(* Logix 5000 project; controller MVI56MCM 1756-L63 rev 15.3; software revision 15.00 *)
// Example Logic for the MVI56-MCM module.

TASK MainTask (continuous, watchdog 500 ms) : MainProgram

MODULES
   Local : 1756-L63 (ICP 0, rev 15.3)
      MVI56MCM : vendor 1 type 0 code 15 (ICP 1, rev 1.1, Output RPI 2 ms)   // ProSoft Technology Modbus communication module for the control logix platform
END_MODULES

TYPE _CmdControl :
STRUCT
   TriggerCmdCntrl : BOOL;   // Trigger command control. User application will activate this trigger
   NumberOfCommands : INT;   // Number of commands per block (1 to 6)
   PortNumber : INT;   // MVI56-MCM Port Number of master port (1 or 2)
   CommandIndex : INT[6];   // Stores the command indexes for command control
   CmdsAddedToQueue : INT;   // Number of commands added to queue
   CmdControlBlockID : INT;   // Temporary variable to calculate control block ID
   CmdCntrlPending : BOOL;   // Auxiliary control command - prevents a second request before acknowledgment is received
END_STRUCT
END_TYPE

TYPE _CoilArray :   // Conversion to INT values
STRUCT
   Boolean : BOOL[416];   // Conversion from Bool to INT data types
END_STRUCT
END_TYPE

TYPE _EventCmd :
STRUCT
   EventCmdTrigger : BOOL;   // Trigger for event command. User ladder must set this bit to initiate event command
   EventCmdPending : BOOL;   // Set after the ladder has sent an event cmd to the module and is waiting for the status to be returned
   PortNumber : INT;   // Module master port number associated to this request (1 or 2)
   SlaveAddress : INT;   // Slave target modbus address
   InternalDBAddress : INT;   // Internal database address
   PointCount : INT;   // Number of points for this command
   SwapCode : INT;   // Swap code (0= no swap, 1=swap words, 2=swap words and bytes, 3=swap bytes)
   ModbusFunctionCode : INT;   // Modbus function code
   DeviceDBAddress : INT;   // Modbus register address in target modbus slave
   EventCmdStatusReturned : INT;   // (0=Fail, 1=Sucess)
   EventBlockID : INT;   // Temporary variable to calculate event block ID
END_STRUCT
END_TYPE

TYPE _Passthru :
STRUCT
   MBOffset : INT;
   MBOffsetBit : INT;
   MBMsgLen : INT;
   MBMsg : SINT[500];
   MBControl1 : CONTROL;
   MBControl2 : CONTROL;
   MBScratch : INT[3];
   MBCoil : _CoilArray;
END_STRUCT
END_TYPE

TYPE _SlavePollStatus :   // This object contains all of the Slave Polling status (used when the port is used as a master)
STRUCT
   Port1Slave0Read : BOOL;
   Port1Slave128Read : BOOL;
   Port2Slave0Read : BOOL;
   Port2Slave128Read : BOOL;
   P1Slaves : INT[256];   // P1 Slave Status
   P2Slaves : INT[256];   // P2 Slave Status
END_STRUCT
END_TYPE

TYPE _Util :   // This object contains optional elements for the module.
STRUCT
   CmdControl : _CmdControl;   // Allows for a disabled command to be sent to a device (MASTER)
   EventCmd : _EventCmd;   // Allows a command defined in ladder to be sent to a device (MASTER)
   SlavePollStat : _SlavePollStatus;   // Request slave poll status for the port (MASTER).
   Passthru : _Passthru;   // Contains PassThru objects required when PortX.Type is set to a value between 2-4.
END_STRUCT
END_TYPE

TYPE MCMBlkStat :   // This object is used to store the block transfer statistics for the module.
STRUCT
   Read : INT;   // Total number of read block transfers
   Write : INT;   // Total number of write block transfers
   Parse : INT;   // Total number of blocks parsed
   Event : INT;   // Total number of event blocks received
   Cmd : INT;   // Total number of command blocks received
   Err : INT;   // Total number of block transfer errors
END_STRUCT
END_TYPE

TYPE MCMCmd :   // This object is used to contain the attributes to define a master command. An array of these objects is used for each port.
STRUCT
   Enable : INT;   // 0=Disable,1=Continuous,2=Event Command
   IntAddress : INT;   // Module's internal address associated with the command
   PollInt : INT;   // Minimum number of seconds between issuance of command (0-65535 Sec)
   Count : INT;   // Number of registers associated with the command
   Swap : INT;   // Swap code used with command
   Node : INT;   // Node address of the target device on the network
   Func : INT;   // Function code for the command
   DevAddress : INT;   // Address in device associated with the command
END_STRUCT
END_TYPE

TYPE MCMCONFIG :
STRUCT
   ModDef : MCMModule;   // Module Defintion
   Port1 : MCMPort;   // Port 1 configuration settings
   Port2 : MCMPort;   // Port 2 configuration settings
   Port1MasterCmd : MCMCmd[100];   // Master commands for Port 1 (ignore if port is configured for slave mode)
   Port2MasterCmd : MCMCmd[100];   // Master commands for Port 2 (ignore if port is configured for slave mode)
END_STRUCT
END_TYPE

TYPE MCMCONTROL :
STRUCT
   WarmBoot : BOOL;
   ColdBoot : BOOL;
   BPLastRead : INT;   // Index of last read block
   BPLastWrite : INT;   // Index of last write block
   BlockIndex : INT;   // Computed block offset for data table
END_STRUCT
END_TYPE

TYPE MCMDATA :   // Contains Read Data (data read from the module to the processor) and Write Data (data written from the processor to the module)
STRUCT
   ReadData : INT[600];   // Data read from the module to the processor
   WriteData : INT[600];   // Data written from the processor to the module
END_STRUCT
END_TYPE

TYPE MCMModule :   // This object contains the information used to define the data movement between the module and the processor.
STRUCT
   WriteStartReg : INT;   // Start reg to transfer from PLC to module
   WriteRegCnt : INT;   // Number of registers to write from PLC
   ReadStartReg : INT;   // Start reg to transfer from module to PLC
   ReadRegCnt : INT;   // Number of registers to transfer from module
   BPFail : INT;   // Determines module operation if BP fails 0=continue,>0=number of retries before comm shutdown
   ErrStatPtr : INT;   // Internal DB start register for status data (-1=Ignore)
END_STRUCT
END_TYPE

TYPE MCMModuleDef :
STRUCT
   CONFIG : MCMCONFIG;   // Module and port configuration
   DATA : MCMDATA;   // Modbus data transferred between module and processor
   STATUS : MCMSTATUS;   // Status information in each read block
   CONTROL : MCMCONTROL;   // Optional requests from the processor to the module
   _UTIL : _Util;   // Variables for internal ladder usage - should not be accessed by user application
END_STRUCT
END_TYPE

TYPE MCMPort :   // The serial port configuration for the MVI56MCM module.
STRUCT
   Enabled : INT;   // O=Port Disabled,1=Port Enabled
   Type : INT;   // 0=Master, 1=Slave, 2=Slave: pass-through, 3=Slave: formatted pass-through/data swapped, 4=Slave: form. pass-through
   FloatFlag : INT;   // 0=No floating-point data, 1=Use floating-point data
   FloatStart : INT;   // Register offset in message for floating-point data
   FloatOffset : INT;   // Internal DB offset to start of floating-point data
   Protocol : INT;   // 0=Modbus RTU, 1=Modbus ASCII
   Baudrate : INT;   // Baudrate for port (110 to 115.2K)
   Parity : INT;   // 0=None, 1=Odd, 2=Even, 3=Mark, 4=Space
   DataBits : INT;   // 5 to 8 data bits
   StopBits : INT;   // 1 or 2 stop bits
   RTSOn : INT;   // 0-65535 mSec delay before data
   RTSOff : INT;   // 0-65535 mSec delay after data
   MinResp : INT;   // 0-65535 mSec minimum time before response to request
   UseCTS : INT;   // 0=No, 1=Yes to use CTS modem line
   SlaveID : INT;   // 1-255 Modbus Node Address (Slave)
   BitInOffset : INT;   // Internal DB offset to bit input data (Slave)
   WordInOffset : INT;   // Internal DB offset to word input data (Slave)
   OutOffset : INT;   // Internal DB offset to bit output data (Slave)
   HoldOffset : INT;   // Internal DB offset to holding register data (Slave)
   CmdCount : INT;   // Command list count (Master)
   MinCmdDelay : INT;   // 0-65535 mSec minimum time between each command (Master)
   CmdErrPtr : INT;   // Internal DB location to place command error list (Master)
   RespTO : INT;   // 0-65535 mSec response timeout for command (Master)
   RetryCount : INT;   // Retry count for failed request (Master)
   ErrorDelayCntr : INT;   // 0-65535 Command cycle count if error (Master)
   Reserved : INT;   // Reserved (Previously was UseGuardBand parameter)
   InterCharacterDelay : INT;   // 0-65535 mSec time between characters to signal end of message
   Fcn99Offset : INT;   // Internal DB offset to function 99 counter
END_STRUCT
END_TYPE

TYPE MCMPortErrors :   // This object is used to store the port statistics for an MVI56-MCM port.
STRUCT
   CmdReq : INT;   // Total number of command list requests sent
   CmdResp : INT;   // Total number of command list responses received
   CmdErr : INT;   // Total number of command list errors
   Requests : INT;   // Total number of requests for port
   Responses : INT;   // Total number of responses for port
   ErrSent : INT;   // Total number of errors sent
   ErrRec : INT;   // Total number of errors received
END_STRUCT
END_TYPE

TYPE MCMSTATUS :   // This status data is returned on each read block and can be used to detect proper module operation.
STRUCT
   PassCnt : INT;   // Program cycle counter
   Product : INT[2];   // Product Name
   Rev : INT[2];   // Revision Level Number
   OP : INT[2];   // Operating Level Number
   Run : INT[2];   // Run Number
   Prt1Errs : MCMPortErrors;   // Port 1 error statistics
   Prt2Errs : MCMPortErrors;   // Port 2 error statistics
   Blk : MCMBlkStat;   // Block transfer statistics
   Port1LastErr : INT;   // Last command index that received an error on Port 1
   Port1PreviousErr : INT;   // Previous Command index that received an error on Port 1
   Port2LastErr : INT;   // Last command index that received an error on Port 2
   Port2PreviousErr : INT;   // Previous Command index that received an error on Port 2
END_STRUCT
END_TYPE

VAR_GLOBAL   (* controller tags *)
   MCM : MCMModuleDef;
        ._UTIL.PASSTHRU.MBCONTROL1.LEN   // Number of words
        ._UTIL.PASSTHRU.MBSCRATCH[2]   // Moves value
        ._UTIL.PASSTHRU.MBMSGLEN   // Copies write message length to MBMsgLen field
        ._UTIL.PASSTHRU.MBOFFSET   // Word Address
        ._UTIL.PASSTHRU.MBMSG[0]   // Copies the rest of the modbus write message from the master to the MBMsg field
        ._UTIL.PASSTHRU.MBOFFSETBIT   // Sets up bit to be changed
        .DATA.WRITEDATA[0]   // Copies changed data back to WriteData array
        ._UTIL.PASSTHRU.MBCOIL   // Copies WriteData to MBCoil array
        ._UTIL.PASSTHRU.MBCONTROL2.LEN   // Number of words
        ._UTIL.PASSTHRU.MBCONTROL1   // AND's new data with bit mask
        ._UTIL.PASSTHRU.MBCONTROL2   // New data ANDed with mask and ORed with existing data
   MJFAULTS : DINT[12] := ([0] := 450621270, [1] := 191890, [3] := 236704315, [4] := 191890);
END_VAR

PROGRAM MainProgram   (* main routine MainRoutine *)

ROUTINE _PassThru   (* ladder *)
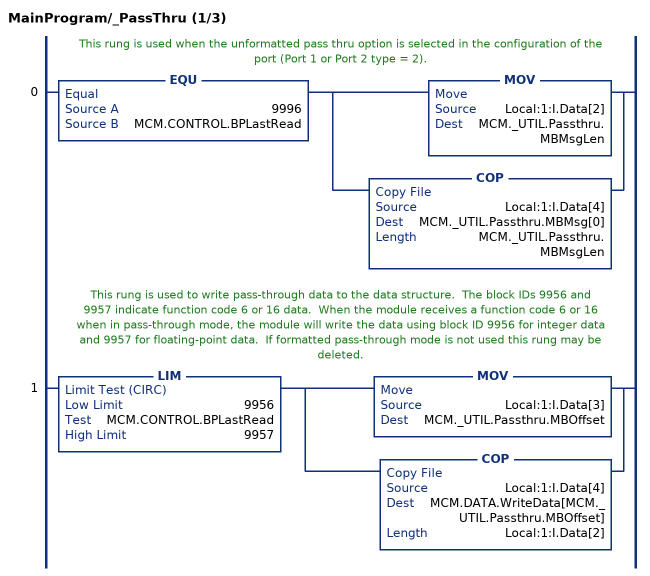
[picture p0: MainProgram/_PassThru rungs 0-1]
   // This rung is used when the unformatted pass thru option is selected in the configuration of the port (Port 1 or Port 2 type = 2).
   0: EQU(9996,MCM.CONTROL.BPLastRead)[MOV(Local:1:I.Data[2],MCM._UTIL.Passthru.MBMsgLen) ,COP(Local:1:I.Data[4],MCM._UTIL.Passthru.MBMsg[0],MCM._UTIL.Passthru.MBMsgLen) ];
   // This rung is used to write pass-through data to the data structure.  The block IDs 9956 and 9957 indicate function code 6 or 16 data.  When the module receives a function code 6 or 16 when in pass-through mode, the module will write the data using block ID 9956 for integer data and 9957 for floating-point data.  If formatted pass-through mode is not used this rung may be deleted.
   1: LIM(9956,MCM.CONTROL.BPLastRead,9957)[MOV(Local:1:I.Data[3],MCM._UTIL.Passthru.MBOffset) ,COP(Local:1:I.Data[4],MCM.DATA.WriteData[MCM._UTIL.Passthru.MBOffset],Local:1:I.Data[2]) ];
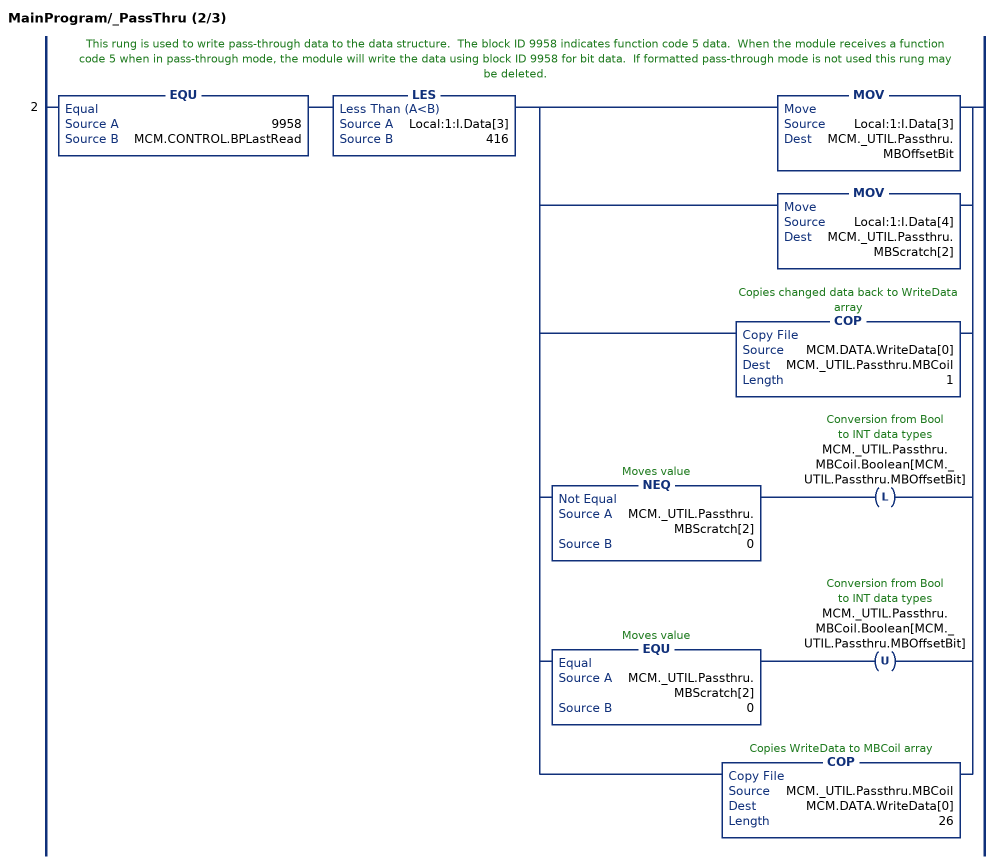
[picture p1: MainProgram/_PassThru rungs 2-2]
   // This rung is used to write pass-through data to the data structure.  The block ID 9958 indicates function code 5 data.  When the module receives a function code 5 when in pass-through mode, the module will write the data using block ID 9958 for bit data.  If formatted pass-through mode is not used this rung may be deleted.
   2: EQU(9958,MCM.CONTROL.BPLastRead)LES(Local:1:I.Data[3],416)[MOV(Local:1:I.Data[3],MCM._UTIL.Passthru.MBOffsetBit) ,MOV(Local:1:I.Data[4],MCM._UTIL.Passthru.MBScratch[2]) ,COP(MCM.DATA.WriteData[0],MCM._UTIL.Passthru.MBCoil,1) ,NEQ(MCM._UTIL.Passthru.MBScratch[2],0) OTL(MCM._UTIL.Passthru.MBCoil.Boolean[MCM._UTIL.Passthru.MBOffsetBit]) ,EQU(MCM._UTIL.Passthru.MBScratch[2],0) OTU(MCM._UTIL.Passthru.MBCoil.Boolean[MCM._UTIL.Passthru.MBOffsetBit]) ,COP(MCM._UTIL.Passthru.MBCoil,MCM.DATA.WriteData[0],26) ];
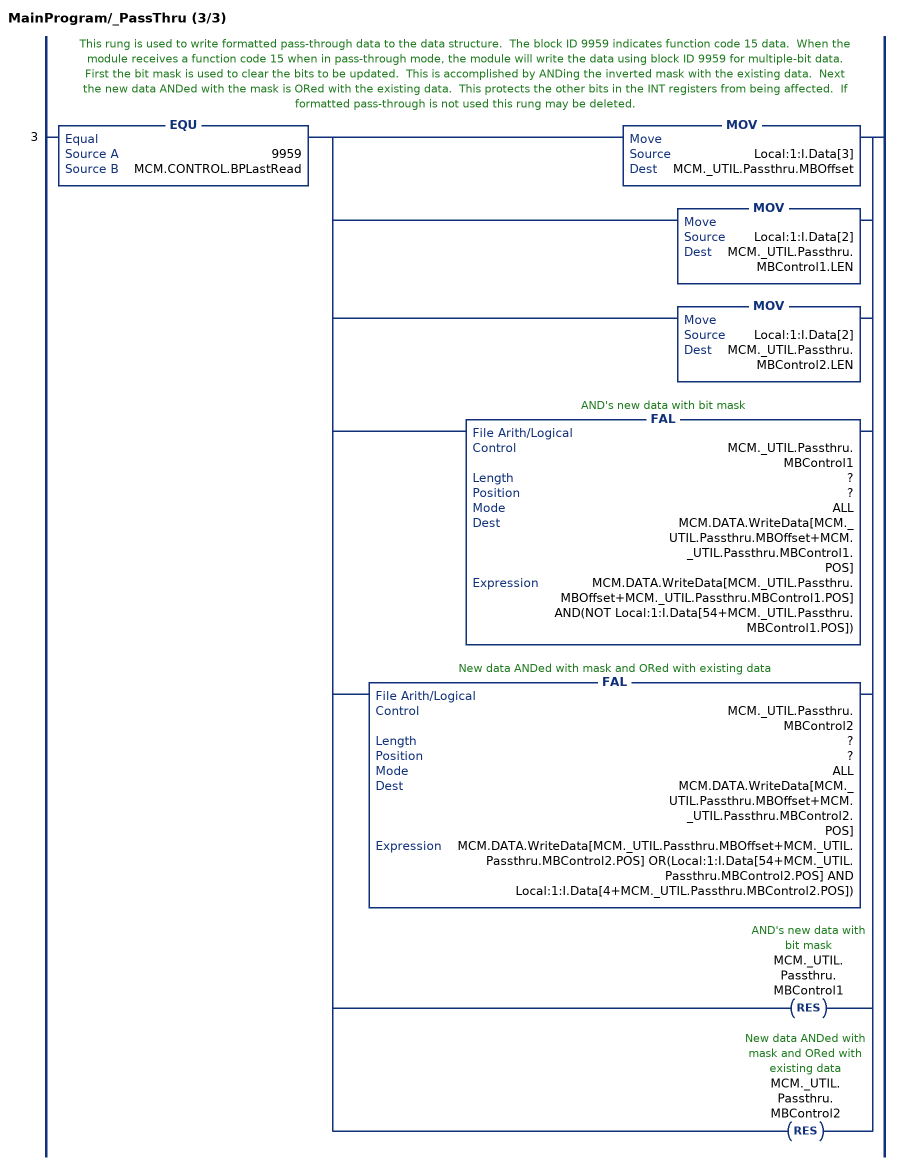
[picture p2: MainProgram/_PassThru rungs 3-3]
   // This rung is used to write formatted pass-through data to the data structure.  The block ID 9959 indicates function code 15 data.  When the module receives a function code 15 when in pass-through mode, the module will write the data using block ID 9959 for multiple-bit data.  First the bit mask is used to clear the bits to be updated.  This is accomplished by ANDing the inverted mask with the existing data.  Next the new data ANDed with the mask is ORed with the existing data.  This protects the other bits in the INT registers from being affected.  If formatted pass-through is not used this rung may be deleted.
   3: EQU(9959,MCM.CONTROL.BPLastRead)[MOV(Local:1:I.Data[3],MCM._UTIL.Passthru.MBOffset) ,MOV(Local:1:I.Data[2],MCM._UTIL.Passthru.MBControl1.LEN) ,MOV(Local:1:I.Data[2],MCM._UTIL.Passthru.MBControl2.LEN) ,FAL(MCM._UTIL.Passthru.MBControl1,?,?,ALL,MCM.DATA.WriteData[MCM._UTIL.Passthru.MBOffset+MCM._UTIL.Passthru.MBControl1.POS],MCM.DATA.WriteData[MCM._UTIL.Passthru.MBOffset+MCM._UTIL.Passthru.MBControl1.POS] AND(NOT Local:1:I.Data[54+MCM._UTIL.Passthru.MBControl1.POS])) ,FAL(MCM._UTIL.Passthru.MBControl2,?,?,ALL,MCM.DATA.WriteData[MCM._UTIL.Passthru.MBOffset+MCM._UTIL.Passthru.MBControl2.POS],MCM.DATA.WriteData[MCM._UTIL.Passthru.MBOffset+MCM._UTIL.Passthru.MBControl2.POS] OR(Local:1:I.Data[54+MCM._UTIL.Passthru.MBControl2.POS] AND Local:1:I.Data[4+MCM._UTIL.Passthru.MBControl2.POS])) ,RES(MCM._UTIL.Passthru.MBControl1) ,RES(MCM._UTIL.Passthru.MBControl2) ];
END_ROUTINE

ROUTINE _ReadControl   (* ladder *)
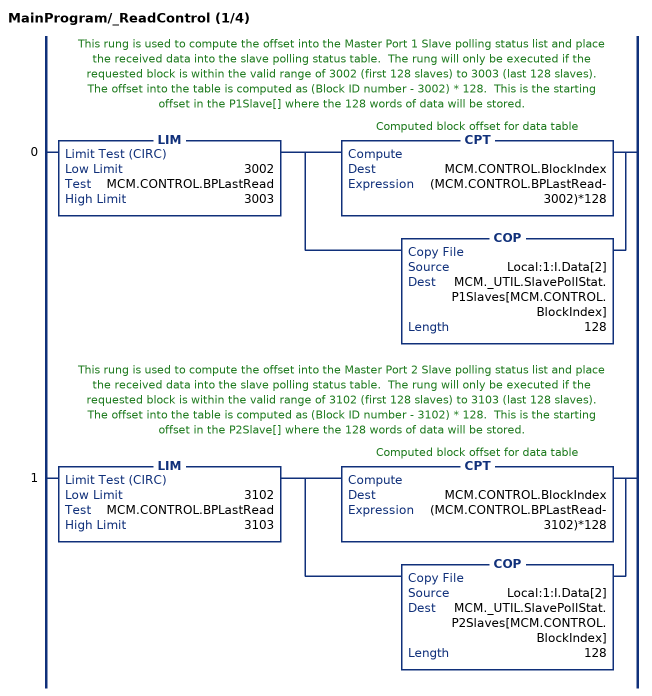
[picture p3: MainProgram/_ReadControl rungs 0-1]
   // This rung is used to compute the offset into the Master Port 1 Slave polling status list and place the received data into the slave polling status table.  The rung will only be executed if the requested block is within the valid range of 3002 (first 128 slaves) to 3003 (last 128 slaves).  The offset into the table is computed as (Block ID number - 3002) * 128.  This is the starting offset in the P1Slave[] where the 128 words of data will be stored.
   0: LIM(3002,MCM.CONTROL.BPLastRead,3003)[CPT(MCM.CONTROL.BlockIndex,(MCM.CONTROL.BPLastRead-3002)*128) ,COP(Local:1:I.Data[2],MCM._UTIL.SlavePollStat.P1Slaves[MCM.CONTROL.BlockIndex],128) ];
   // This rung is used to compute the offset into the Master Port 2 Slave polling status list and place the received data into the slave polling status table.  The rung will only be executed if the requested block is within the valid range of 3102 (first 128 slaves) to 3103 (last 128 slaves).  The offset into the table is computed as (Block ID number - 3102) * 128.  This is the starting offset in the P2Slave[] where the 128 words of data will be stored.
   1: LIM(3102,MCM.CONTROL.BPLastRead,3103)[CPT(MCM.CONTROL.BlockIndex,(MCM.CONTROL.BPLastRead-3102)*128) ,COP(Local:1:I.Data[2],MCM._UTIL.SlavePollStat.P2Slaves[MCM.CONTROL.BlockIndex],128) ];
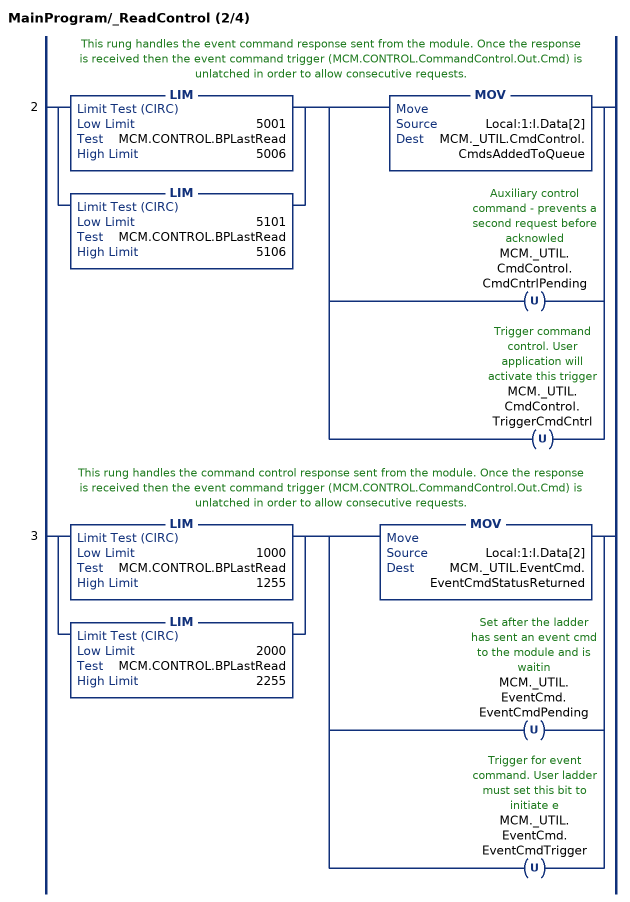
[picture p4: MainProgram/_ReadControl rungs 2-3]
   // This rung handles the event command response sent from the module. Once the response is received then the event command trigger (MCM.CONTROL.CommandControl.Out.Cmd) is unlatched in order to allow consecutive requests.
   2: [LIM(5001,MCM.CONTROL.BPLastRead,5006) ,LIM(5101,MCM.CONTROL.BPLastRead,5106) ][MOV(Local:1:I.Data[2],MCM._UTIL.CmdControl.CmdsAddedToQueue) ,OTU(MCM._UTIL.CmdControl.CmdCntrlPending) ,OTU(MCM._UTIL.CmdControl.TriggerCmdCntrl) ];
   // This rung handles the command control response sent from the module. Once the response is received then the event command trigger (MCM.CONTROL.CommandControl.Out.Cmd) is unlatched in order to allow consecutive requests.
   3: [LIM(1000,MCM.CONTROL.BPLastRead,1255) ,LIM(2000,MCM.CONTROL.BPLastRead,2255) ][MOV(Local:1:I.Data[2],MCM._UTIL.EventCmd.EventCmdStatusReturned) ,OTU(MCM._UTIL.EventCmd.EventCmdPending) ,OTU(MCM._UTIL.EventCmd.EventCmdTrigger) ];
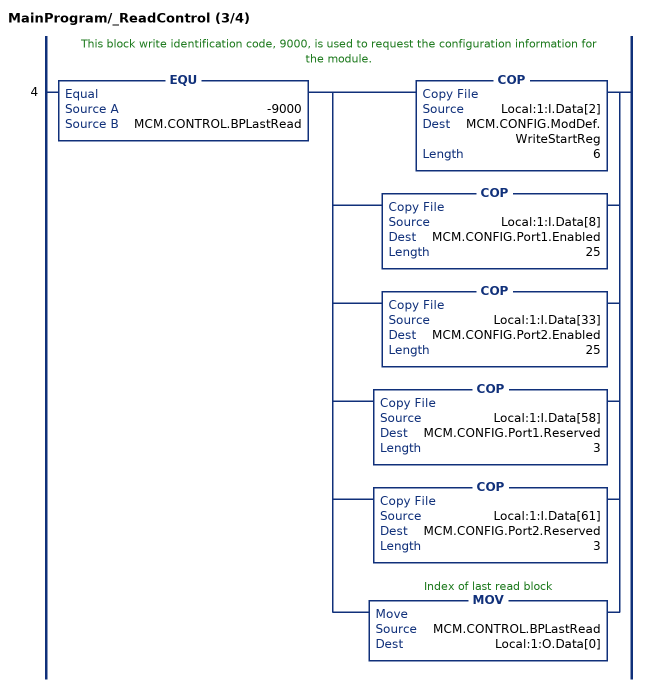
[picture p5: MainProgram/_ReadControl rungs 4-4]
   // This block write identification code, 9000, is used to request the configuration information for the module.
   4: EQU(-9000,MCM.CONTROL.BPLastRead)[COP(Local:1:I.Data[2],MCM.CONFIG.ModDef.WriteStartReg,6) ,COP(Local:1:I.Data[8],MCM.CONFIG.Port1.Enabled,25) ,COP(Local:1:I.Data[33],MCM.CONFIG.Port2.Enabled,25) ,COP(Local:1:I.Data[58],MCM.CONFIG.Port1.Reserved,3) ,COP(Local:1:I.Data[61],MCM.CONFIG.Port2.Reserved,3) ,MOV(MCM.CONTROL.BPLastRead,Local:1:O.Data[0]) ];
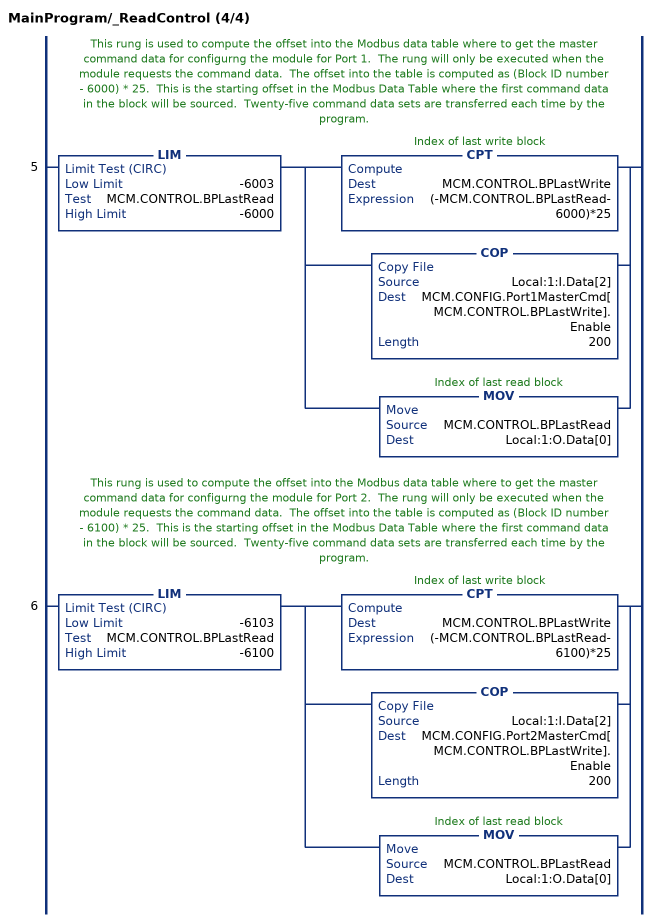
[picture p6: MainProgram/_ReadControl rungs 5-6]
   // This rung is used to compute the offset into the Modbus data table where to get the master command data for configurng the module for Port 1.  The rung will only be executed when the module requests the command data.  The offset into the table is computed as (Block ID number - 6000) * 25.  This is the starting offset in the Modbus Data Table where the first command data in the block will be sourced.  Twenty-five command data sets are transferred each time by the program.
   5: LIM(-6003,MCM.CONTROL.BPLastRead,-6000)[CPT(MCM.CONTROL.BPLastWrite,(-MCM.CONTROL.BPLastRead-6000)*25) ,COP(Local:1:I.Data[2],MCM.CONFIG.Port1MasterCmd[MCM.CONTROL.BPLastWrite].Enable,200) ,MOV(MCM.CONTROL.BPLastRead,Local:1:O.Data[0]) ];
   // This rung is used to compute the offset into the Modbus data table where to get the master command data for configurng the module for Port 2.  The rung will only be executed when the module requests the command data.  The offset into the table is computed as (Block ID number - 6100) * 25.  This is the starting offset in the Modbus Data Table where the first command data in the block will be sourced.  Twenty-five command data sets are transferred each time by the program.
   6: LIM(-6103,MCM.CONTROL.BPLastRead,-6100)[CPT(MCM.CONTROL.BPLastWrite,(-MCM.CONTROL.BPLastRead-6100)*25) ,COP(Local:1:I.Data[2],MCM.CONFIG.Port2MasterCmd[MCM.CONTROL.BPLastWrite].Enable,200) ,MOV(MCM.CONTROL.BPLastRead,Local:1:O.Data[0]) ];
END_ROUTINE

ROUTINE _WriteControl   (* ladder *)
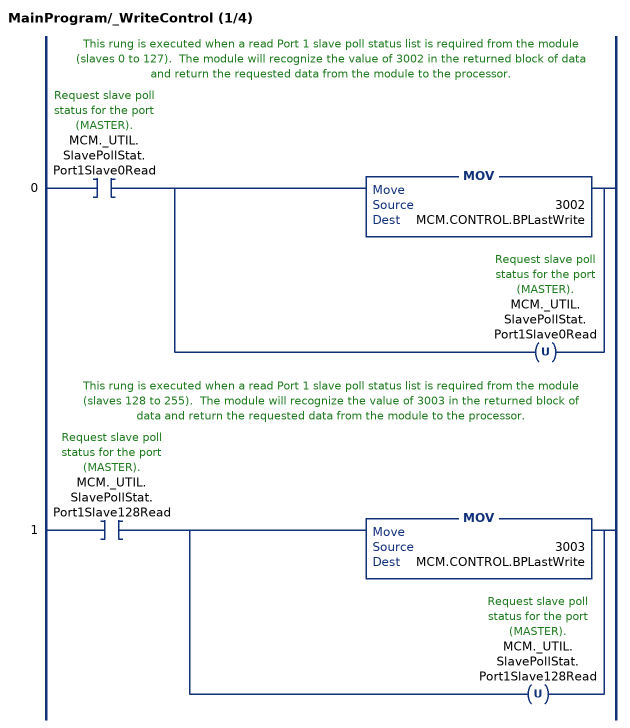
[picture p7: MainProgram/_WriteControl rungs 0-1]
   // This rung is executed when a read Port 1 slave poll status list is required from the module (slaves 0 to 127).  The module will recognize the value of 3002 in the returned block of data and return the requested data from the module to the processor.
   0: XIC(MCM._UTIL.SlavePollStat.Port1Slave0Read)[MOV(3002,MCM.CONTROL.BPLastWrite) ,OTU(MCM._UTIL.SlavePollStat.Port1Slave0Read) ];
   // This rung is executed when a read Port 1 slave poll status list is required from the module (slaves 128 to 255).  The module will recognize the value of 3003 in the returned block of data and return the requested data from the module to the processor.
   1: XIC(MCM._UTIL.SlavePollStat.Port1Slave128Read)[MOV(3003,MCM.CONTROL.BPLastWrite) ,OTU(MCM._UTIL.SlavePollStat.Port1Slave128Read) ];
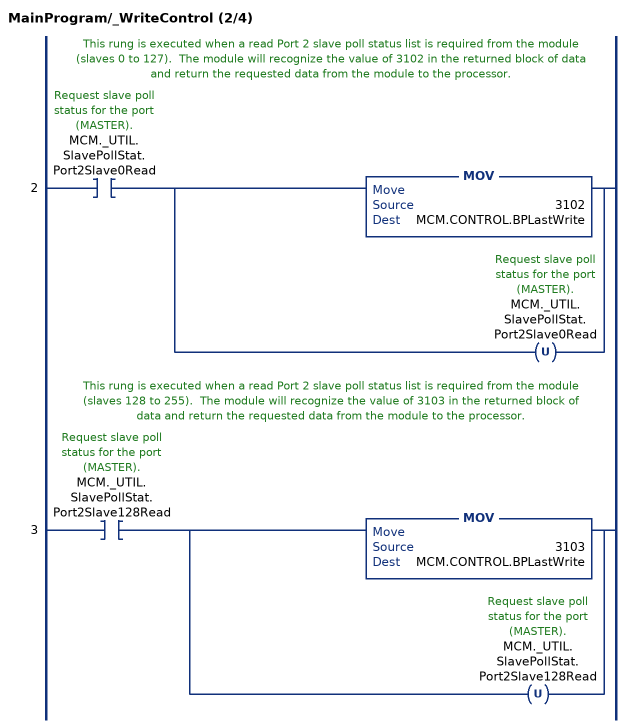
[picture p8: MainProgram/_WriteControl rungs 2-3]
   // This rung is executed when a read Port 2 slave poll status list is required from the module (slaves 0 to 127).  The module will recognize the value of 3102 in the returned block of data and return the requested data from the module to the processor.
   2: XIC(MCM._UTIL.SlavePollStat.Port2Slave0Read)[MOV(3102,MCM.CONTROL.BPLastWrite) ,OTU(MCM._UTIL.SlavePollStat.Port2Slave0Read) ];
   // This rung is executed when a read Port 2 slave poll status list is required from the module (slaves 128 to 255).  The module will recognize the value of 3103 in the returned block of data and return the requested data from the module to the processor.
   3: XIC(MCM._UTIL.SlavePollStat.Port2Slave128Read)[MOV(3103,MCM.CONTROL.BPLastWrite) ,OTU(MCM._UTIL.SlavePollStat.Port2Slave128Read) ];
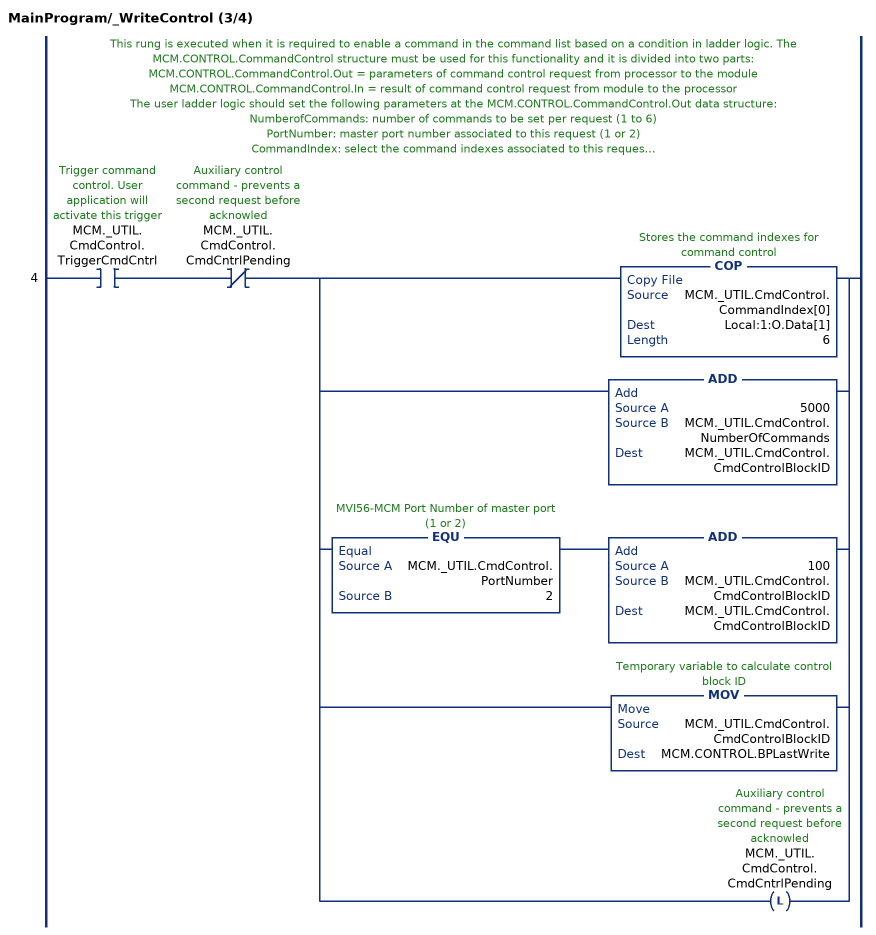
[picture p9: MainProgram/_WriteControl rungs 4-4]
   // This rung is executed when it is required to enable a command in the command list based on a condition in ladder logic. The MCM.CONTROL.CommandControl structure must be used for this functionality and it is divided into two parts:
   // MCM.CONTROL.CommandControl.Out = parameters of command control request from processor to the module
   // MCM.CONTROL.CommandControl.In = result of command control request from module to the processor
   // The user ladder logic should set the following parameters at the MCM.CONTROL.CommandControl.Out data structure:
   // NumberofCommands: number of commands to be set per request (1 to 6)
   // PortNumber: master port number associated to this request (1 or 2)
   // CommandIndex: select the command indexes associated to this request
   // The MCM._UTIL.SlavePollStat.Port1Slave0Read bit is the actual trigger that will initiate the request. MCM._UTIL.CmdControl.CmdCntrlPending is a auxiliary variable that guarantees that the request will only be performed once
   4: XIC(MCM._UTIL.CmdControl.TriggerCmdCntrl)XIO(MCM._UTIL.CmdControl.CmdCntrlPending)[COP(MCM._UTIL.CmdControl.CommandIndex[0],Local:1:O.Data[1],6) ,ADD(5000,MCM._UTIL.CmdControl.NumberOfCommands,MCM._UTIL.CmdControl.CmdControlBlockID) ,EQU(MCM._UTIL.CmdControl.PortNumber,2) ADD(100,MCM._UTIL.CmdControl.CmdControlBlockID,MCM._UTIL.CmdControl.CmdControlBlockID) ,MOV(MCM._UTIL.CmdControl.CmdControlBlockID,MCM.CONTROL.BPLastWrite) ,OTL(MCM._UTIL.CmdControl.CmdCntrlPending) ];
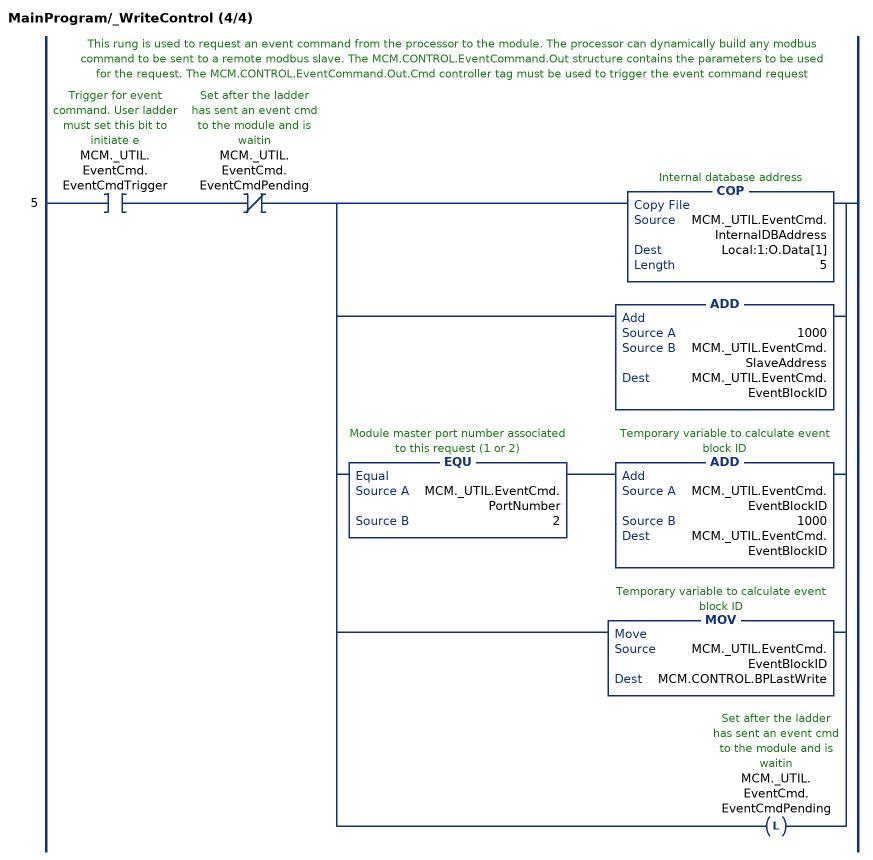
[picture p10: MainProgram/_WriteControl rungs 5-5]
   // This rung is used to request an event command from the processor to the module. The processor can dynamically build any modbus command to be sent to a remote modbus slave. The MCM.CONTROL.EventCommand.Out structure contains the parameters to be used for the request. The MCM.CONTROL.EventCommand.Out.Cmd controller tag must be used to trigger the event command request
   5: XIC(MCM._UTIL.EventCmd.EventCmdTrigger)XIO(MCM._UTIL.EventCmd.EventCmdPending)[COP(MCM._UTIL.EventCmd.InternalDBAddress,Local:1:O.Data[1],5) ,ADD(1000,MCM._UTIL.EventCmd.SlaveAddress,MCM._UTIL.EventCmd.EventBlockID) ,EQU(MCM._UTIL.EventCmd.PortNumber,2) ADD(MCM._UTIL.EventCmd.EventBlockID,1000,MCM._UTIL.EventCmd.EventBlockID) ,MOV(MCM._UTIL.EventCmd.EventBlockID,MCM.CONTROL.BPLastWrite) ,OTL(MCM._UTIL.EventCmd.EventCmdPending) ];
END_ROUTINE

ROUTINE MainRoutine   (* ladder *)
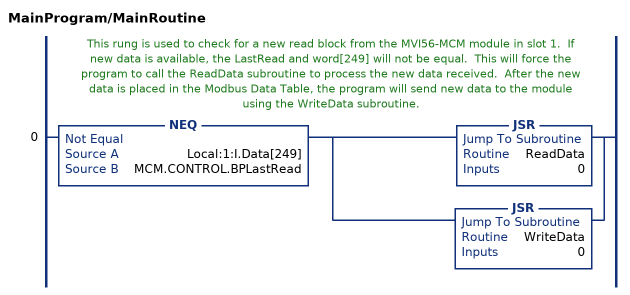
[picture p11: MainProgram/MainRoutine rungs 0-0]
   // This rung is used to check for a new read block from the MVI56-MCM module in slot 1.  If new data is available, the LastRead and word[249] will not be equal.  This will force the program to call the ReadData subroutine to process the new data received.  After the new data is placed in the Modbus Data Table, the program will send new data to the module using the WriteData subroutine.
   0: NEQ(Local:1:I.Data[249],MCM.CONTROL.BPLastRead)[JSR(ReadData,0) ,JSR(WriteData,0) ];
END_ROUTINE

ROUTINE ReadData   (* ladder *)
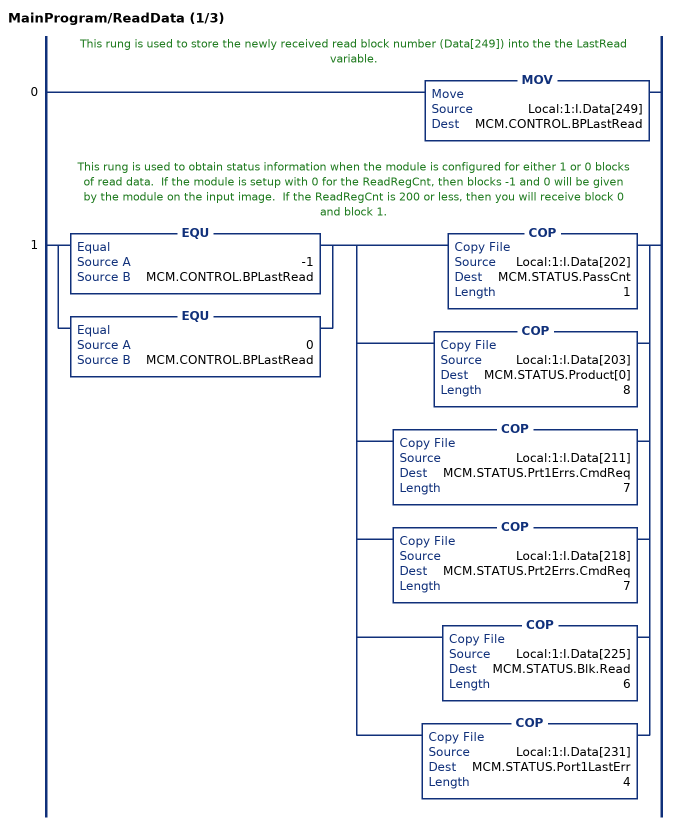
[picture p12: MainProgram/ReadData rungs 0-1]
   // This rung is used to store the newly received read block number (Data[249]) into the the LastRead variable.
   0: MOV(Local:1:I.Data[249],MCM.CONTROL.BPLastRead);
   // This rung is used to obtain status information when the module is configured for either 1 or 0 blocks of read data.  If the module is setup with 0 for the ReadRegCnt, then blocks -1 and 0 will be given by the module on the input image.  If the ReadRegCnt is 200 or less, then you will receive block 0 and block 1.
   1: [EQU(-1,MCM.CONTROL.BPLastRead) ,EQU(0,MCM.CONTROL.BPLastRead) ][COP(Local:1:I.Data[202],MCM.STATUS.PassCnt,1) ,COP(Local:1:I.Data[203],MCM.STATUS.Product[0],8) ,COP(Local:1:I.Data[211],MCM.STATUS.Prt1Errs.CmdReq,7) ,COP(Local:1:I.Data[218],MCM.STATUS.Prt2Errs.CmdReq,7) ,COP(Local:1:I.Data[225],MCM.STATUS.Blk.Read,6) ,COP(Local:1:I.Data[231],MCM.STATUS.Port1LastErr,4) ];
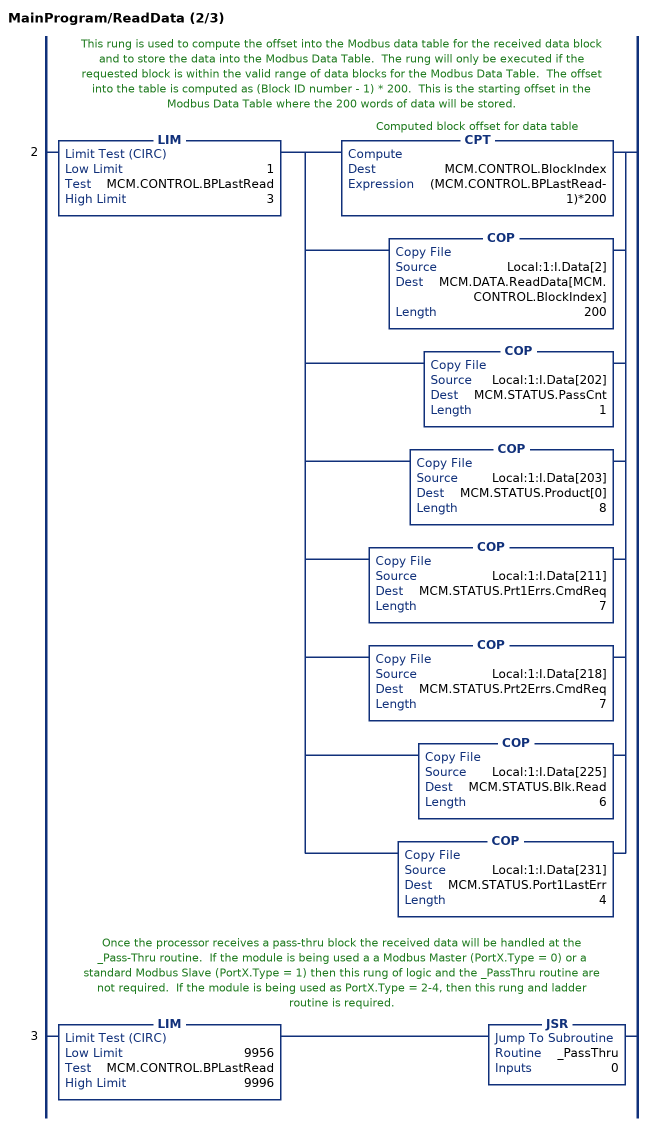
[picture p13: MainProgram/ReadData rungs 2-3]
   // This rung is used to compute the offset into the Modbus data table for the received data block and to store the data into the Modbus Data Table.  The rung will only be executed if the requested block is within the valid range of data blocks for the Modbus Data Table.  The offset into the table is computed as (Block ID number - 1) * 200.  This is the starting offset in the Modbus Data Table where the 200 words of data will be stored.
   2: LIM(1,MCM.CONTROL.BPLastRead,3)[CPT(MCM.CONTROL.BlockIndex,(MCM.CONTROL.BPLastRead-1)*200) ,COP(Local:1:I.Data[2],MCM.DATA.ReadData[MCM.CONTROL.BlockIndex],200) ,COP(Local:1:I.Data[202],MCM.STATUS.PassCnt,1) ,COP(Local:1:I.Data[203],MCM.STATUS.Product[0],8) ,COP(Local:1:I.Data[211],MCM.STATUS.Prt1Errs.CmdReq,7) ,COP(Local:1:I.Data[218],MCM.STATUS.Prt2Errs.CmdReq,7) ,COP(Local:1:I.Data[225],MCM.STATUS.Blk.Read,6) ,COP(Local:1:I.Data[231],MCM.STATUS.Port1LastErr,4) ];
   // Once the processor receives a pass-thru block the received data will be handled at the _Pass-Thru routine.  If the module is being used a a Modbus Master (PortX.Type = 0) or a standard Modbus Slave (PortX.Type = 1) then this rung of logic and the _PassThru routine are not required.  If the module is being used as PortX.Type = 2-4, then this rung and ladder routine is required.
   3: LIM(9956,MCM.CONTROL.BPLastRead,9996)JSR(_PassThru,0);
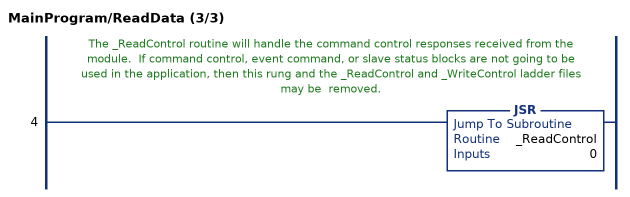
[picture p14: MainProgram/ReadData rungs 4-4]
   // The _ReadControl routine will handle the command control responses received from the module.  If command control, event command, or slave status blocks are not going to be used in the application, then this rung and the _ReadControl and _WriteControl ladder files may be  removed.
   4: JSR(_ReadControl,0);
END_ROUTINE

ROUTINE WriteData   (* ladder *)
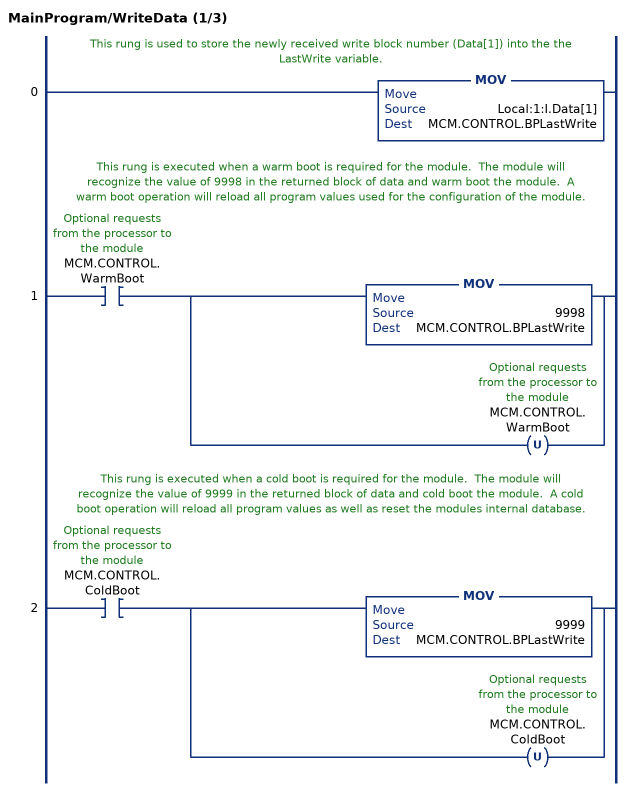
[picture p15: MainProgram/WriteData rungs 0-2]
   // This rung is used to store the newly received write block number (Data[1]) into the the LastWrite variable.
   0: MOV(Local:1:I.Data[1],MCM.CONTROL.BPLastWrite);
   // This rung is executed when a warm boot is required for the module.  The module will recognize the value of 9998 in the returned block of data and warm boot the module.  A warm boot operation will reload all program values used for the configuration of the module.
   1: XIC(MCM.CONTROL.WarmBoot)[MOV(9998,MCM.CONTROL.BPLastWrite) ,OTU(MCM.CONTROL.WarmBoot) ];
   // This rung is executed when a cold boot is required for the module.  The module will recognize the value of 9999 in the returned block of data and cold boot the module.  A cold boot operation will reload all program values as well as reset the modules internal database.
   2: XIC(MCM.CONTROL.ColdBoot)[MOV(9999,MCM.CONTROL.BPLastWrite) ,OTU(MCM.CONTROL.ColdBoot) ];
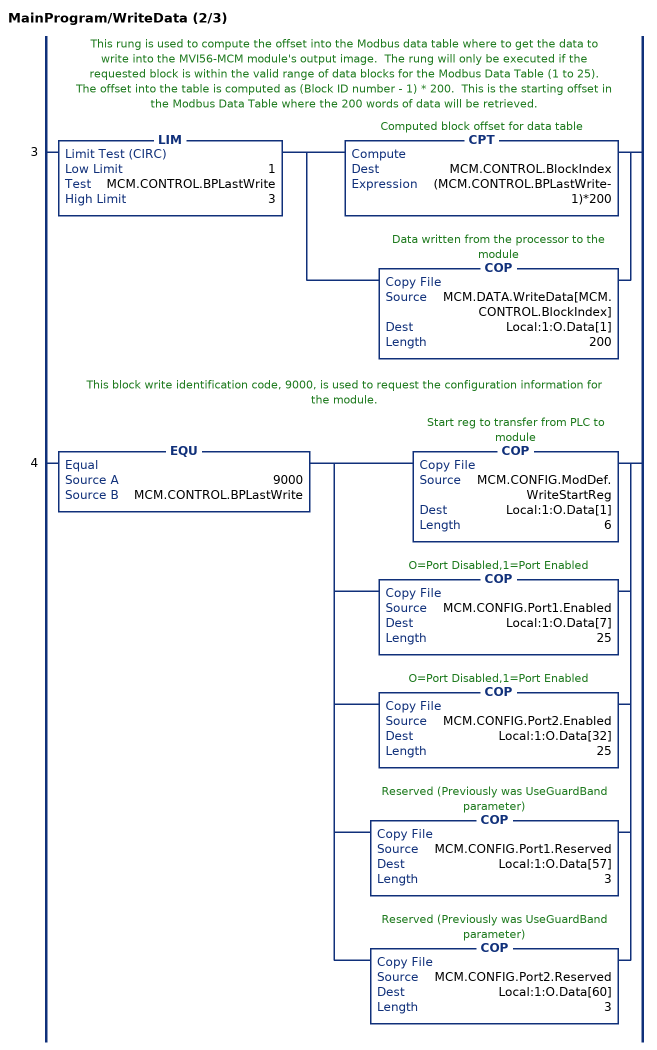
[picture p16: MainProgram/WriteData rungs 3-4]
   // This rung is used to compute the offset into the Modbus data table where to get the data to write into the MVI56-MCM module's output image.  The rung will only be executed if the requested block is within the valid range of data blocks for the Modbus Data Table (1 to 25).  The offset into the table is computed as (Block ID number - 1) * 200.  This is the starting offset in the Modbus Data Table where the 200 words of data will be retrieved.
   3: LIM(1,MCM.CONTROL.BPLastWrite,3)[CPT(MCM.CONTROL.BlockIndex,(MCM.CONTROL.BPLastWrite-1)*200) ,COP(MCM.DATA.WriteData[MCM.CONTROL.BlockIndex],Local:1:O.Data[1],200) ];
   // This block write identification code, 9000, is used to request the configuration information for the module.
   4: EQU(9000,MCM.CONTROL.BPLastWrite)[COP(MCM.CONFIG.ModDef.WriteStartReg,Local:1:O.Data[1],6) ,COP(MCM.CONFIG.Port1.Enabled,Local:1:O.Data[7],25) ,COP(MCM.CONFIG.Port2.Enabled,Local:1:O.Data[32],25) ,COP(MCM.CONFIG.Port1.Reserved,Local:1:O.Data[57],3) ,COP(MCM.CONFIG.Port2.Reserved,Local:1:O.Data[60],3) ];
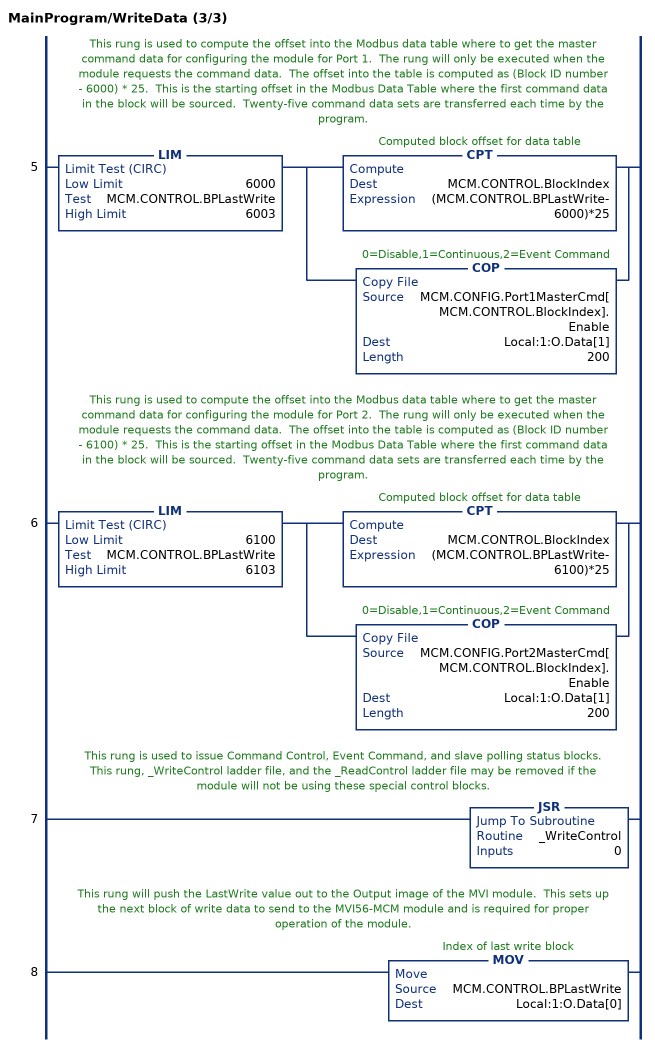
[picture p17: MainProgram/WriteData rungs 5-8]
   // This rung is used to compute the offset into the Modbus data table where to get the master command data for configuring the module for Port 1.  The rung will only be executed when the module requests the command data.  The offset into the table is computed as (Block ID number - 6000) * 25.  This is the starting offset in the Modbus Data Table where the first command data in the block will be sourced.  Twenty-five command data sets are transferred each time by the program.
   5: LIM(6000,MCM.CONTROL.BPLastWrite,6003)[CPT(MCM.CONTROL.BlockIndex,(MCM.CONTROL.BPLastWrite-6000)*25) ,COP(MCM.CONFIG.Port1MasterCmd[MCM.CONTROL.BlockIndex].Enable,Local:1:O.Data[1],200) ];
   // This rung is used to compute the offset into the Modbus data table where to get the master command data for configuring the module for Port 2.  The rung will only be executed when the module requests the command data.  The offset into the table is computed as (Block ID number - 6100) * 25.  This is the starting offset in the Modbus Data Table where the first command data in the block will be sourced.  Twenty-five command data sets are transferred each time by the program.
   6: LIM(6100,MCM.CONTROL.BPLastWrite,6103)[CPT(MCM.CONTROL.BlockIndex,(MCM.CONTROL.BPLastWrite-6100)*25) ,COP(MCM.CONFIG.Port2MasterCmd[MCM.CONTROL.BlockIndex].Enable,Local:1:O.Data[1],200) ];
   // This rung is used to issue Command Control, Event Command, and slave polling status blocks.  This rung, _WriteControl ladder file, and the _ReadControl ladder file may be removed if the module will not be using these special control blocks.
   7: JSR(_WriteControl,0);
   // This rung will push the LastWrite value out to the Output image of the MVI module.  This sets up the next block of write data to send to the MVI56-MCM module and is required for proper operation of the module.
   8: MOV(MCM.CONTROL.BPLastWrite,Local:1:O.Data[0]);
END_ROUTINE
END_PROGRAM

PROGRAM StartUp   (* main routine PowerUp *)

ROUTINE PowerUp   (* ladder *)
// This routine is executed each time the module is powered up or restarted.
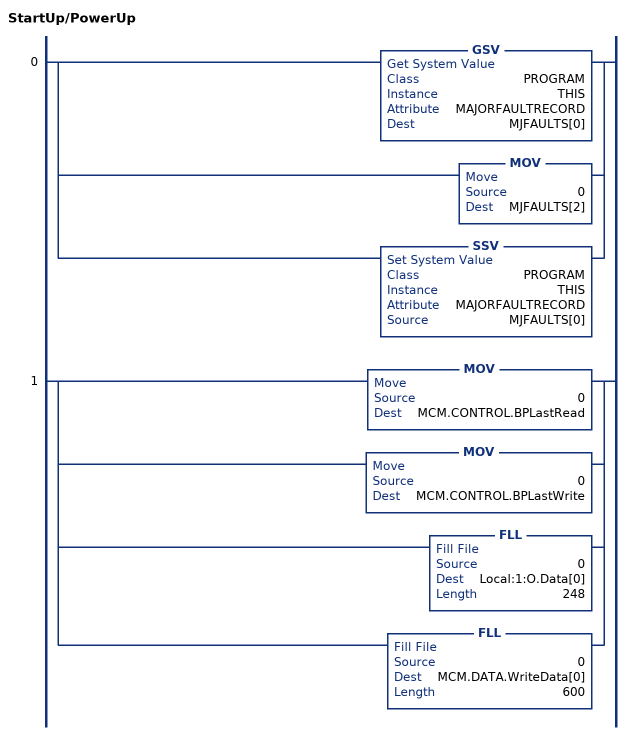
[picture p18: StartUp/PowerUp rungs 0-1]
   0: [GSV(PROGRAM,THIS,MAJORFAULTRECORD,MJFAULTS[0]) ,MOV(0,MJFAULTS[2]) ,SSV(PROGRAM,THIS,MAJORFAULTRECORD,MJFAULTS[0]) ];
   1: [MOV(0,MCM.CONTROL.BPLastRead) ,MOV(0,MCM.CONTROL.BPLastWrite) ,FLL(0,Local:1:O.Data[0],248) ,FLL(0,MCM.DATA.WriteData[0],600) ];
END_ROUTINE
END_PROGRAM
